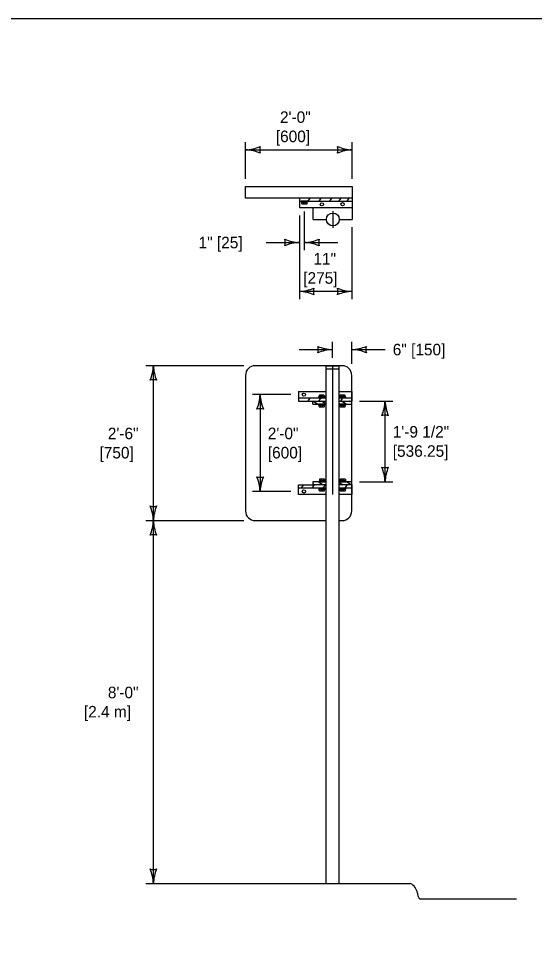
# Model space of a CAD drawing. Extents: x 49991.4 to 50021, y 49987.6 to 50011.4.
# Drawn here: x 50002.173 to 50004.856, y 49994.159 to 49998.999 of the extents above; entities that cross this region are included whole.
import ezdxf

# ---------------------------------------------------------------- set-up
doc = ezdxf.new("R2010")
doc.units = 0
for name, color, linetype in [('Level 1', 7, 'Continuous'), ('Level 2', 7, 'Continuous'), ('Level 3', 7, 'Continuous'), ('Level 4', 7, 'Continuous'), ('Level 5', 7, 'Continuous')]:
    doc.layers.add(name, color=color, linetype=linetype)

msp = doc.modelspace()

# ---------------------------------------------------------------- linework, layer by layer
at = {"layer": 'Level 1'}
for p, q in [((50003.6335, 49998.0629), (50003.635, 49998.0651)), ((50003.6335, 49998.0651), (50003.6335, 49998.0161)), ((50003.6335, 49998.0493), (50003.7726, 49998.0493)), ((50003.6796, 49998.0493), (50003.6903, 49998.0651)), ((50003.7365, 49998.0493), (50003.7471, 49998.0651)), ((50003.7726, 49998.0493), (50003.9072, 49998.0493)), ((50003.7916, 49998.0497), (50003.8021, 49998.0651)), ((50003.8394, 49998.0493), (50003.8501, 49998.0651)), ((50003.8394, 49998.0493), (50003.9083, 49998.0493)), ((50003.8824, 49998.0492), (50003.8932, 49998.0651)), ((50003.9083, 49998.0651), (50003.9083, 49997.9548)), ((50003.6335, 49998.0161), (50003.7054, 49998.0161)), ((50003.646, 49998.0383), (50003.646, 49998.0446)), ((50003.6486, 49998.0357), (50003.6712, 49998.0357)), ((50003.6552, 49998.0382), (50003.6552, 49998.0446)), ((50003.6644, 49998.0382), (50003.6644, 49998.0446)), ((50003.6737, 49998.0383), (50003.6737, 49998.0446)), ((50003.7054, 49997.9548), (50003.7054, 49998.0161)), ((50003.7054, 49998.0161), (50003.8394, 49998.0161)), ((50003.8394, 49998.0161), (50003.9083, 49998.0161)), ((50003.7054, 49997.9548), (50003.7742, 49997.9548)), ((50003.8414, 49997.9548), (50003.9083, 49997.9548)), ((50003.8556, 49997.1943), (50003.4037, 49997.1943)), ((50003.7719, 49997.1943), (50003.8384, 49997.1943)), ((50003.7719, 49997.1943), (50003.7719, 49994.5026)), ((50003.8384, 49997.1943), (50003.8384, 49994.5026)), ((50003.3535, 49997.144), (50003.3535, 49996.4389)), ((50003.7719, 49997.1777), (50003.8384, 49997.1777)), ((50003.9059, 49996.4389), (50003.9059, 49997.144)), ((50003.6296, 49997.0602), (50003.7719, 49997.0602)), ((50003.6296, 49997.0602), (50003.6296, 49997.0103)), ((50003.7358, 49997.0382), (50003.7358, 49997.032)), ((50003.7608, 49997.0408), (50003.7382, 49997.0408)), ((50003.7609, 49997.0408), (50003.7382, 49997.0408)), ((50003.745, 49997.0408), (50003.745, 49997.032)), ((50003.7543, 49997.0408), (50003.7543, 49997.032)), ((50003.7634, 49997.0382), (50003.7634, 49997.032)), ((50003.8384, 49997.0602), (50003.9059, 49997.0602)), ((50003.8441, 49997.0382), (50003.8441, 49997.032)), ((50003.8691, 49997.0408), (50003.8465, 49997.0408)), ((50003.8692, 49997.0408), (50003.8465, 49997.0408)), ((50003.8533, 49997.0408), (50003.8533, 49997.032)), ((50003.8626, 49997.0408), (50003.8626, 49997.032)), ((50003.8717, 49997.0382), (50003.8717, 49997.032)), ((50003.9059, 49997.0602), (50003.9059, 49997.0103)), ((50003.6296, 49997.027), (50003.7719, 49997.027)), ((50003.6296, 49997.0223), (50003.6328, 49997.027)), ((50003.6296, 49997.0103), (50003.7033, 49997.0103)), ((50003.6784, 49997.0103), (50003.6897, 49997.027)), ((50003.7033, 49996.9936), (50003.7033, 49997.0103)), ((50003.7033, 49997.0103), (50003.7719, 49997.0103)), ((50003.7271, 49996.9939), (50003.7033, 49997.01)), ((50003.7033, 49996.9936), (50003.7719, 49996.9936)), ((50003.7352, 49997.0103), (50003.7465, 49997.027)), ((50003.7352, 49997.0103), (50003.7461, 49997.0264)), ((50003.7359, 49996.9823), (50003.7359, 49996.9884)), ((50003.7451, 49996.9797), (50003.7451, 49996.9884)), ((50003.7722, 49996.994), (50003.7483, 49997.0103)), ((50003.7544, 49996.9797), (50003.7544, 49996.9884)), ((50003.7636, 49996.9823), (50003.7636, 49996.9884)), ((50003.8384, 49997.027), (50003.9059, 49997.027)), ((50003.8384, 49997.0103), (50003.9059, 49997.0103)), ((50003.8384, 49997.0103), (50003.9059, 49997.0103)), ((50003.8384, 49996.9936), (50003.9059, 49996.9936)), ((50003.8448, 49996.9823), (50003.8448, 49996.9885)), ((50003.849, 49997.0103), (50003.8603, 49997.027)), ((50003.8764, 49996.9936), (50003.8519, 49997.0101)), ((50003.8539, 49996.9798), (50003.8539, 49996.9885)), ((50003.8632, 49996.9798), (50003.8632, 49996.9885)), ((50003.8725, 49996.9823), (50003.8725, 49996.9885)), ((50003.9059, 49997.0042), (50003.8968, 49997.0103)), ((50003.7384, 49996.9797), (50003.7611, 49996.9797)), ((50003.7385, 49996.9797), (50003.7611, 49996.9797)), ((50003.8473, 49996.9798), (50003.87, 49996.9798)), ((50003.8474, 49996.9798), (50003.87, 49996.9798)), ((50003.738, 49996.6018), (50003.738, 49996.5956)), ((50003.7631, 49996.6043), (50003.7405, 49996.6043)), ((50003.7632, 49996.6043), (50003.7405, 49996.6043)), ((50003.7473, 49996.6043), (50003.7473, 49996.5956)), ((50003.7566, 49996.6043), (50003.7566, 49996.5956)), ((50003.7657, 49996.6018), (50003.7657, 49996.5956)), ((50003.8453, 49996.6019), (50003.8453, 49996.5957)), ((50003.8704, 49996.6044), (50003.8478, 49996.6044)), ((50003.8705, 49996.6044), (50003.8478, 49996.6044)), ((50003.8545, 49996.6044), (50003.8545, 49996.5957)), ((50003.8638, 49996.6044), (50003.8638, 49996.5957)), ((50003.8729, 49996.6019), (50003.8729, 49996.5957)), ((50003.6296, 49996.5239), (50003.6296, 49996.5738)), ((50003.6296, 49996.5738), (50003.703, 49996.5738)), ((50003.7719, 49996.5571), (50003.6296, 49996.5571)), ((50003.6438, 49996.5571), (50003.6551, 49996.5738)), ((50003.7008, 49996.557), (50003.712, 49996.5738)), ((50003.7719, 49996.5906), (50003.703, 49996.5906)), ((50003.703, 49996.5906), (50003.703, 49996.5738)), ((50003.703, 49996.5799), (50003.7121, 49996.5738)), ((50003.7719, 49996.5738), (50003.703, 49996.5738)), ((50003.7324, 49996.5907), (50003.7569, 49996.574)), ((50003.7372, 49996.5459), (50003.7372, 49996.5521)), ((50003.7463, 49996.5433), (50003.7463, 49996.5521)), ((50003.7556, 49996.5433), (50003.7556, 49996.5521)), ((50003.7576, 49996.5571), (50003.7689, 49996.5738)), ((50003.7648, 49996.5459), (50003.7648, 49996.5521)), ((50003.9059, 49996.5906), (50003.8384, 49996.5906)), ((50003.8384, 49996.5889), (50003.8606, 49996.5738)), ((50003.9059, 49996.5738), (50003.8384, 49996.5738)), ((50003.9059, 49996.5571), (50003.8384, 49996.5571)), ((50003.8455, 49996.5459), (50003.8455, 49996.5521)), ((50003.8546, 49996.5433), (50003.8546, 49996.5521)), ((50003.8639, 49996.5433), (50003.8639, 49996.5521)), ((50003.8715, 49996.5573), (50003.8826, 49996.5738)), ((50003.8731, 49996.5459), (50003.8731, 49996.5521)), ((50003.8812, 49996.5906), (50003.9059, 49996.5739)), ((50003.9059, 49996.5738), (50003.9059, 49996.5239)), ((50003.7719, 49996.5239), (50003.6296, 49996.5239)), ((50003.7397, 49996.5433), (50003.7624, 49996.5433)), ((50003.7397, 49996.5433), (50003.7624, 49996.5433)), ((50003.9059, 49996.5239), (50003.8384, 49996.5239)), ((50003.848, 49996.5433), (50003.8707, 49996.5433)), ((50003.8481, 49996.5433), (50003.8707, 49996.5433)), ((50003.4037, 49996.3887), (50003.7719, 49996.3887)), ((50003.8384, 49996.3887), (50003.8556, 49996.3887)), ((50002.8338, 49994.5009), (50004.2105, 49994.5009)), ((50004.2625, 49994.4217), (50004.7625, 49994.4217))]:
    msp.add_line(p, q, dxfattribs=at)
for points in [[(49999.3835, 49998.9992), (50016.7501, 49998.9992), (50016.7501, 49987.7988), (49999.3835, 49987.7988)], [(50003.9083, 49998.1268), (50003.9083, 49998.0651), (50003.3535, 49998.0651), (50003.3535, 49998.1268)], [(50003.6433, 49998.0493), (50003.6433, 49998.0446), (50003.6761, 49998.0446), (50003.6761, 49998.0493)], [(50003.7332, 49996.9933), (50003.7332, 49996.9886), (50003.7661, 49996.9886), (50003.7661, 49996.9933)], [(50003.7662, 49997.0272), (50003.7662, 49997.0318), (50003.7333, 49997.0318), (50003.7333, 49997.0272)], [(50003.8745, 49997.0272), (50003.8745, 49997.0318), (50003.8416, 49997.0318), (50003.8416, 49997.0272)], [(50003.8421, 49996.9934), (50003.8421, 49996.9887), (50003.8749, 49996.9887), (50003.8749, 49996.9934)], [(50003.7344, 49996.5569), (50003.7344, 49996.5523), (50003.7673, 49996.5523), (50003.7673, 49996.5569)], [(50003.7684, 49996.5908), (50003.7684, 49996.5954), (50003.7356, 49996.5954), (50003.7356, 49996.5908)], [(50003.8427, 49996.5569), (50003.8427, 49996.5523), (50003.8756, 49996.5523), (50003.8756, 49996.5569)], [(50003.8757, 49996.5909), (50003.8757, 49996.5955), (50003.8428, 49996.5955), (50003.8428, 49996.5909)]]:
    msp.add_lwpolyline(points, close=True, dxfattribs=at)
for centre, radius in [((50003.7506, 49998.0332), 0.00843), ((50003.858, 49998.034), 0.00843), ((50003.8076, 49997.9548), 0.0333), ((50003.6568, 49997.0436), 0.00843), ((50003.6568, 49996.5405), 0.00843)]:
    msp.add_circle(centre, radius, dxfattribs=at)
for centre, radius, start, end in [((50003.6486, 49998.0382), 0.00257, 180, 270), ((50003.6527, 49998.0382), 0.00257, 270, 0), ((50003.6578, 49998.0382), 0.00257, 180, 270), ((50003.6619, 49998.0382), 0.00257, 270, 0), ((50003.667, 49998.0382), 0.00257, 180, 270), ((50003.6711, 49998.0382), 0.00257, 270, 0), ((50003.4037, 49997.144), 0.0503, 90, 180), ((50003.8556, 49997.144), 0.0503, 0, 90), ((50003.7383, 49997.0382), 0.00257, 90, 180), ((50003.7424, 49997.0382), 0.00257, 0, 90), ((50003.7475, 49997.0382), 0.00257, 90, 180), ((50003.7516, 49997.0382), 0.00257, 0, 90), ((50003.7568, 49997.0382), 0.00257, 90, 180), ((50003.7608, 49997.0382), 0.00257, 0, 90), ((50003.8466, 49997.0382), 0.00257, 90, 180), ((50003.8507, 49997.0382), 0.00257, 0, 90), ((50003.8558, 49997.0382), 0.00257, 90, 180), ((50003.8599, 49997.0382), 0.00257, 0, 90), ((50003.8651, 49997.0382), 0.00257, 90, 180), ((50003.8691, 49997.0382), 0.00257, 0, 90), ((50003.7385, 49996.9822), 0.00257, 180, 270), ((50003.7426, 49996.9822), 0.00257, 270, 0), ((50003.7477, 49996.9822), 0.00257, 180, 270), ((50003.7518, 49996.9822), 0.00257, 270, 0), ((50003.757, 49996.9822), 0.00257, 180, 270), ((50003.761, 49996.9822), 0.00257, 270, 0), ((50003.8474, 49996.9823), 0.00257, 180, 270), ((50003.8515, 49996.9823), 0.00257, 270, 0), ((50003.8566, 49996.9823), 0.00257, 180, 270), ((50003.8607, 49996.9823), 0.00257, 270, 0), ((50003.8658, 49996.9823), 0.00257, 180, 270), ((50003.8699, 49996.9823), 0.00257, 270, 0), ((50003.7406, 49996.6018), 0.00257, 90, 180), ((50003.7447, 49996.6018), 0.00257, 0, 90), ((50003.7498, 49996.6018), 0.00257, 90, 180), ((50003.7539, 49996.6018), 0.00257, 0, 90), ((50003.759, 49996.6018), 0.00257, 90, 180), ((50003.7631, 49996.6018), 0.00257, 0, 90), ((50003.8479, 49996.6019), 0.00257, 90, 180), ((50003.8519, 49996.6019), 0.00257, 0, 90), ((50003.8571, 49996.6019), 0.00257, 90, 180), ((50003.8611, 49996.6019), 0.00257, 0, 90), ((50003.8663, 49996.6019), 0.00257, 90, 180), ((50003.8703, 49996.6019), 0.00257, 0, 90), ((50003.7398, 49996.5459), 0.00257, 180, 270), ((50003.7438, 49996.5459), 0.00257, 270, 0), ((50003.749, 49996.5459), 0.00257, 180, 270), ((50003.753, 49996.5459), 0.00257, 270, 0), ((50003.7582, 49996.5459), 0.00257, 180, 270), ((50003.7623, 49996.5459), 0.00257, 270, 0), ((50003.8481, 49996.5459), 0.00257, 180, 270), ((50003.8521, 49996.5459), 0.00257, 270, 0), ((50003.8573, 49996.5459), 0.00257, 180, 270), ((50003.8613, 49996.5459), 0.00257, 270, 0), ((50003.8665, 49996.5459), 0.00257, 180, 270), ((50003.8706, 49996.5459), 0.00257, 270, 0), ((50003.4037, 49996.4389), 0.0503, 180, 270), ((50003.8556, 49996.4389), 0.0503, 270, 0), ((50004.1868, 49994.4448), 0.061, 5.9118, 67.1491), ((50004.3081, 49994.4574), 0.061, 185.9118, 213.2855)]:
    msp.add_arc(centre, radius, start, end, dxfattribs=at)
msp.add_spline([(50004.2571, 49994.4239), (50004.2585, 49994.423), (50004.2601, 49994.4222), (50004.2625, 49994.4217)], degree=3, dxfattribs=at)
at = {"layer": 'Level 3'}
for p, q in [((50003.3535, 49998.1668), (50003.3535, 49998.3568)), ((50003.9083, 49998.1668), (50003.9083, 49998.3568)), ((50003.3535, 49998.3168), (50003.9083, 49998.3168)), ((50003.6335, 49997.9761), (50003.6335, 49997.5404)), ((50003.6599, 49997.7948), (50003.6599, 49997.9957)), ((50003.9083, 49997.5404), (50003.9083, 49997.9148)), ((50003.4601, 49997.8348), (50003.6335, 49997.8348)), ((50003.6599, 49997.8348), (50003.8333, 49997.8348)), ((50003.9083, 49997.5804), (50003.6335, 49997.5804)), ((50003.6317, 49997.2781), (50003.8051, 49997.2781)), ((50003.8051, 49997.2343), (50003.8051, 49997.3181)), ((50003.9059, 49997.204), (50003.9059, 49997.3181)), ((50003.9059, 49997.2781), (50004.0793, 49997.2781)), ((50003.3437, 49997.1943), (50002.8338, 49997.1943)), ((50002.8738, 49996.3887), (50002.8738, 49997.1943)), ((50003.5896, 49997.0436), (50003.3892, 49997.0436)), ((50003.4292, 49997.0436), (50003.4292, 49996.5405)), ((50003.9459, 49997.0103), (50004.1193, 49997.0103)), ((50004.0793, 49996.5906), (50004.0793, 49997.0103)), ((50003.9459, 49996.5906), (50004.1193, 49996.5906)), ((50003.5896, 49996.5405), (50003.3892, 49996.5405)), ((50002.8338, 49996.3887), (50003.3437, 49996.3887)), ((50002.8738, 49994.5009), (50002.8738, 49996.3887))]:
    msp.add_line(p, q, dxfattribs=at)
for centre, radius, start, end in [((50003.342, 49998.5495), 0.233, 272.8273, 292.0772), ((50003.3443, 49998.0947), 0.2223, 67.456, 87.6395), ((50003.4817, 49998.3168), 0.0548, 162.1388, 197.8612), ((50003.9175, 49998.5389), 0.2223, 247.456, 267.6395), ((50003.7801, 49998.3168), 0.0548, 342.1388, 17.8612), ((50003.9198, 49998.0841), 0.233, 92.8273, 112.0772), ((50003.6427, 49998.0569), 0.2223, 247.456, 267.6395), ((50003.5053, 49997.8348), 0.0548, 342.1388, 17.8612), ((50003.645, 49997.6021), 0.233, 92.8273, 112.0772), ((50003.6484, 49998.0675), 0.233, 272.8273, 292.0772), ((50003.6507, 49997.6127), 0.2223, 67.456, 87.6395), ((50003.7881, 49997.8348), 0.0548, 162.1388, 197.8612), ((50003.622, 49997.8131), 0.233, 272.8273, 292.0772), ((50003.6243, 49997.3582), 0.2223, 67.456, 87.6395), ((50003.7617, 49997.5804), 0.0548, 162.1388, 197.8612), ((50003.9175, 49997.8025), 0.2223, 247.456, 267.6395), ((50003.7801, 49997.5804), 0.0548, 342.1388, 17.8612), ((50003.9198, 49997.3477), 0.233, 92.8273, 112.0772), ((50003.8143, 49997.5002), 0.2223, 247.456, 267.6395), ((50003.6769, 49997.2781), 0.0548, 342.1388, 17.8612), ((50003.8166, 49997.0454), 0.233, 92.8273, 112.0772), ((50003.8944, 49997.5108), 0.233, 272.8273, 292.0772), ((50003.8967, 49997.056), 0.2223, 67.456, 87.6395), ((50004.0341, 49997.2781), 0.0548, 162.1388, 197.8612), ((50002.6517, 49997.2035), 0.2223, 337.456, 357.6395), ((50003.1065, 49997.2058), 0.233, 182.8273, 202.0772), ((50002.8738, 49997.0661), 0.0548, 72.1388, 107.8612), ((50003.2071, 49997.0528), 0.2223, 337.456, 357.6395), ((50003.6619, 49997.0551), 0.233, 182.8273, 202.0772), ((50003.8572, 49997.0195), 0.2223, 337.456, 357.6395), ((50004.312, 49997.0218), 0.233, 182.8273, 202.0772), ((50003.4292, 49996.9154), 0.0548, 72.1388, 107.8612), ((50004.0793, 49996.8821), 0.0548, 72.1388, 107.8612), ((50004.0793, 49996.7188), 0.0548, 252.1388, 287.8612), ((50003.8466, 49996.5791), 0.233, 2.8273, 22.0772), ((50004.3014, 49996.5814), 0.2223, 157.456, 177.6395), ((50003.4292, 49996.6687), 0.0548, 252.1388, 287.8612), ((50003.1965, 49996.529), 0.233, 2.8273, 22.0772), ((50003.6513, 49996.5313), 0.2223, 157.456, 177.6395), ((50002.8738, 49996.5169), 0.0548, 252.1388, 287.8612), ((50002.6411, 49996.3772), 0.233, 2.8273, 22.0772), ((50003.0959, 49996.3795), 0.2223, 157.456, 177.6395), ((50002.6517, 49996.3979), 0.2223, 337.456, 357.6395), ((50003.1065, 49996.4002), 0.233, 182.8273, 202.0772), ((50002.8738, 49996.2605), 0.0548, 72.1388, 107.8612), ((50002.8738, 49994.6291), 0.0548, 252.1388, 287.8612), ((50002.6411, 49994.4894), 0.233, 2.8273, 22.0772), ((50003.0959, 49994.4917), 0.2223, 157.456, 177.6395)]:
    msp.add_arc(centre, radius, start, end, dxfattribs=at)
at = {"layer": 'Level 4'}
msp.add_line((50003.8051, 49997.1943), (50003.8051, 49996.5239), dxfattribs=at)
at = {"layer": 'Level 5'}
msp.add_line((50003.8075, 49997.9981), (50003.8075, 49997.9116), dxfattribs=at)

# ---------------------------------------------------------------- texts
at = {"layer": 'Level 2'}
for s, p in [('2\'-0"', (50003.5326, 49998.4568)), ('[600]', (50003.5108, 49998.3568)), ('1" [25]', (50003.109, 49997.8048)), ('11"', (50003.7065, 49997.7204)), ('[275]', (50003.6536, 49997.6204)), ('6" [150]', (50004.1193, 49997.2481)), ('2\'-6"', (50002.6369, 49996.8118)), ('2\'-0"', (50003.4692, 49996.812)), ('1\'-9 1/2"', (50004.1193, 49996.8204)), ('[750]', (50002.5934, 49996.7118)), ('[600]', (50003.4692, 49996.712)), ('[536.25]', (50004.1193, 49996.7204)), ('8\'-0"', (50002.6369, 49995.4648)), ('[2.4 m]', (50002.5124, 49995.3648))]:
    msp.add_text(s, height=0.06, dxfattribs=at).set_placement(p)

doc.saveas('drawing.dxf')
